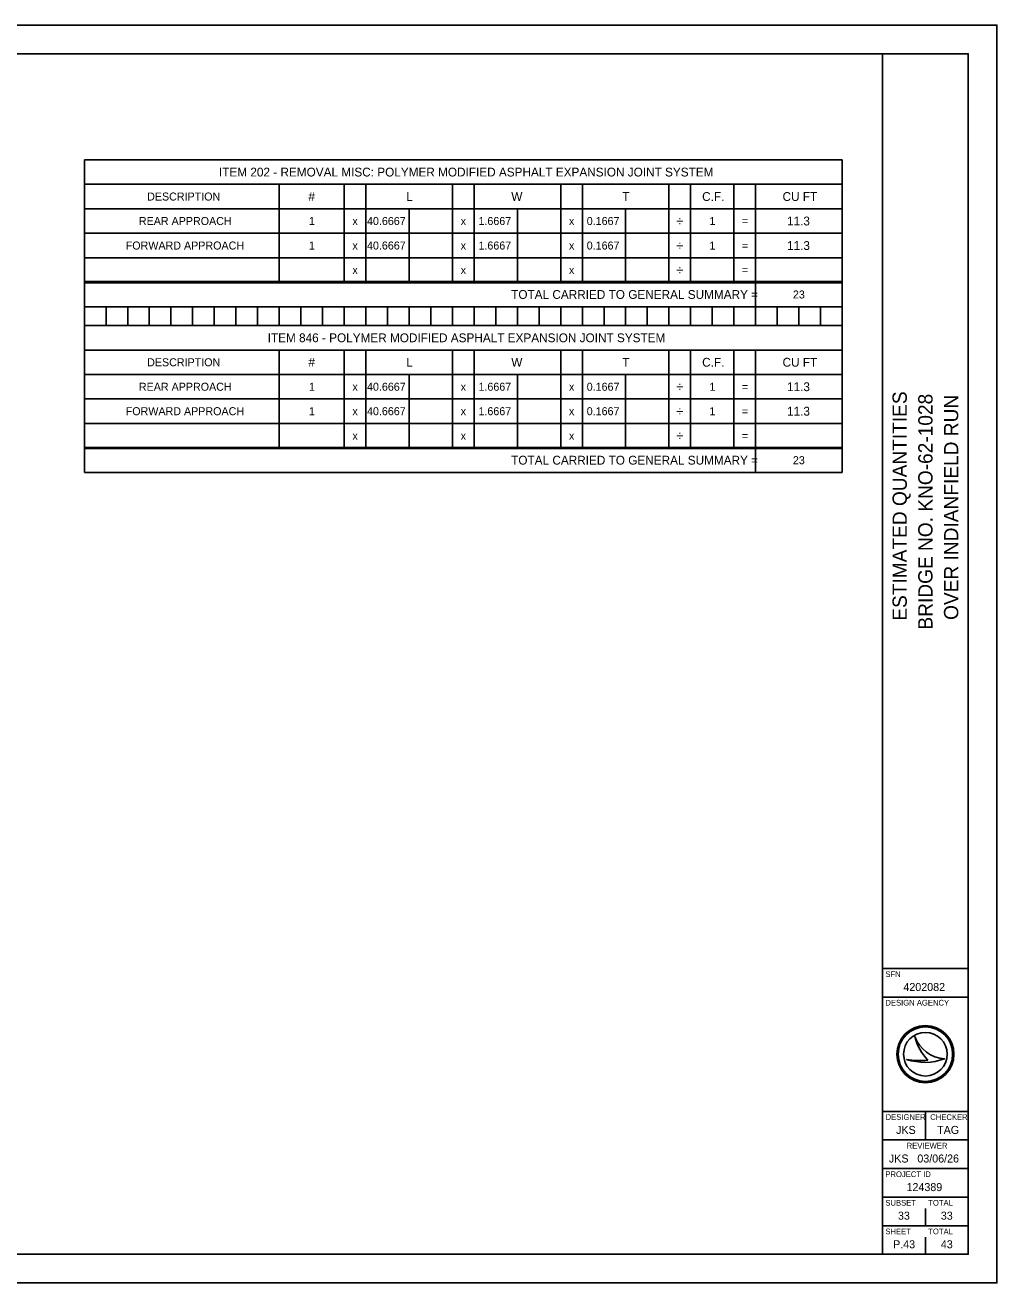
# Model space of a CAD drawing. Extents: x 0 to 34, y 0 to 22.
# Drawn here: x 17 to 34, y 0 to 22 of the extents above; entities that cross this region are included whole.
import ezdxf

# ---------------------------------------------------------------- set-up
doc = ezdxf.new("R2010")
doc.units = 0
for name, color, linetype in [('SH_Border', 7, 'Continuous'), ('SH_Cut_Line', 7, 'Continuous'), ('SH_Data', 7, 'Continuous'), ('SH_Text', 7, 'Continuous')]:
    doc.layers.add(name, color=color, linetype=linetype)

msp = doc.modelspace()

# ---------------------------------------------------------------- linework, layer by layer
at = {"layer": 'SH_Border'}
for p, q in [((32, 0.5), (32, 21.5)), ((32, 5.5), (33.5, 5.5)), ((32, 5), (33.5, 5)), ((32, 3), (33.5, 3)), ((32.75, 3), (32.75, 2.5)), ((32, 2.5), (33.5, 2.5)), ((32, 2), (33.5, 2)), ((32, 1.5), (33.5, 1.5)), ((32, 1), (33.5, 1))]:
    msp.add_line(p, q, dxfattribs=at)
msp.add_lwpolyline([(1.5, 21.5), (33.5, 21.5), (33.5, 0.5), (1.5, 0.5)], close=True, dxfattribs=at)
at = {"layer": 'SH_Cut_Line'}
msp.add_lwpolyline([(0, 0), (34, 0), (34, 22), (0, 22)], close=True, dxfattribs=at)
at = {"layer": 'SH_Data'}
for p, q in [((32.567, 4.31), (32.567, 4.31)), ((32.75, 4), (32.75, 4)), ((32.417, 3.91), (32.417, 3.91)), ((33.087, 3.919), (33.087, 3.919)), ((32.75, 1), (32.75, 1.3)), ((32.375, 0.675), (32.375, 0.675)), ((32.75, 0.5), (32.75, 0.8))]:
    msp.add_line(p, q, dxfattribs=at)
for radius in [0.5, 0.477, 0.477, 0.382]:
    msp.add_circle((32.75, 4), radius, dxfattribs=at)
for centre, radius, start, end in [((33.116, 4.498), 0.58, 198.9257, 198.9319), ((33.347, 4.47), 0.796, 191.6379, 191.6421), ((33.116, 4.498), 0.58, 198.9319, 267.1657), ((33.347, 4.47), 0.796, 191.6421, 226.0947), ((32.739, 4.87), 1.013, 251.4576, 290.0832), ((32.648, 5.154), 1.266, 259.4964, 259.4995), ((32.739, 4.87), 1.013, 251.4527, 251.4576), ((32.648, 5.154), 1.266, 259.4995, 276.6672)]:
    msp.add_arc(centre, radius, start, end, dxfattribs=at)
at = {"layer": 'SH_Text'}
for p, q in [((18.036, 19.644), (31.295, 19.644)), ((18.036, 19.644), (18.036, 17.492)), ((31.295, 19.644), (31.295, 17.492)), ((18.036, 19.216), (31.295, 19.216)), ((21.445, 19.216), (21.445, 17.514)), ((22.582, 19.216), (22.582, 17.514)), ((22.961, 19.216), (22.961, 17.514)), ((24.476, 19.216), (24.476, 17.514)), ((24.855, 19.216), (24.855, 17.514)), ((26.37, 19.216), (26.37, 17.514)), ((26.749, 19.216), (26.749, 17.514)), ((28.264, 19.216), (28.264, 17.514)), ((28.643, 19.216), (28.643, 17.514)), ((29.401, 19.216), (29.401, 17.514)), ((29.779, 19.216), (29.779, 17.514)), ((18.036, 18.788), (31.295, 18.788)), ((23.718, 18.788), (23.718, 17.514)), ((25.612, 18.788), (25.612, 17.514)), ((27.506, 18.788), (27.506, 17.514)), ((18.036, 18.36), (31.295, 18.36)), ((18.036, 17.931), (31.295, 17.931)), ((18.036, 17.514), (31.295, 17.514)), ((18.036, 17.514), (18.036, 14.593)), ((18.036, 17.492), (31.295, 17.492)), ((29.779, 17.492), (29.779, 17.075)), ((31.295, 17.514), (31.295, 14.593)), ((18.036, 17.075), (31.295, 17.075)), ((18.036, 16.745), (31.295, 16.745)), ((18.036, 16.317), (31.295, 16.317)), ((21.445, 16.317), (21.445, 14.615)), ((22.582, 16.317), (22.582, 14.615)), ((22.961, 16.317), (22.961, 14.615)), ((24.476, 16.317), (24.476, 14.615)), ((24.855, 16.317), (24.855, 14.615)), ((26.37, 16.317), (26.37, 14.615)), ((26.749, 16.317), (26.749, 14.615)), ((28.264, 16.317), (28.264, 14.615)), ((28.643, 16.317), (28.643, 14.615)), ((29.401, 16.317), (29.401, 14.615)), ((29.779, 16.317), (29.779, 14.615)), ((18.036, 15.889), (31.295, 15.889)), ((23.718, 15.889), (23.718, 14.615)), ((25.612, 15.889), (25.612, 14.615)), ((27.506, 15.889), (27.506, 14.615)), ((18.036, 15.461), (31.295, 15.461)), ((18.036, 15.032), (31.295, 15.032)), ((18.036, 14.615), (31.295, 14.615)), ((18.036, 14.615), (18.036, 14.176)), ((18.036, 14.593), (31.295, 14.593)), ((29.779, 14.593), (29.779, 14.176)), ((31.295, 14.615), (31.295, 14.176)), ((18.036, 14.176), (31.295, 14.176))]:
    msp.add_line(p, q, dxfattribs=at)
for points in [[(18.036, 17.075), (18.415, 17.075), (18.415, 16.745), (18.036, 16.745)], [(18.415, 17.075), (18.794, 17.075), (18.794, 16.745), (18.415, 16.745)], [(18.794, 17.075), (19.172, 17.075), (19.172, 16.745), (18.794, 16.745)], [(19.172, 17.075), (19.551, 17.075), (19.551, 16.745), (19.172, 16.745)], [(19.551, 17.075), (19.93, 17.075), (19.93, 16.745), (19.551, 16.745)], [(19.93, 17.075), (20.309, 17.075), (20.309, 16.745), (19.93, 16.745)], [(20.309, 17.075), (20.688, 17.075), (20.688, 16.745), (20.309, 16.745)], [(20.688, 17.075), (21.066, 17.075), (21.066, 16.745), (20.688, 16.745)], [(21.066, 17.075), (21.445, 17.075), (21.445, 16.745), (21.066, 16.745)], [(21.445, 17.075), (21.824, 17.075), (21.824, 16.745), (21.445, 16.745)], [(21.824, 17.075), (22.203, 17.075), (22.203, 16.745), (21.824, 16.745)], [(22.203, 17.075), (22.582, 17.075), (22.582, 16.745), (22.203, 16.745)], [(22.582, 17.075), (22.961, 17.075), (22.961, 16.745), (22.582, 16.745)], [(22.961, 17.075), (23.339, 17.075), (23.339, 16.745), (22.961, 16.745)], [(23.339, 17.075), (23.718, 17.075), (23.718, 16.745), (23.339, 16.745)], [(23.718, 17.075), (24.097, 17.075), (24.097, 16.745), (23.718, 16.745)], [(24.097, 17.075), (24.476, 17.075), (24.476, 16.745), (24.097, 16.745)], [(24.476, 17.075), (24.855, 17.075), (24.855, 16.745), (24.476, 16.745)], [(24.855, 17.075), (25.234, 17.075), (25.234, 16.745), (24.855, 16.745)], [(25.234, 17.075), (25.612, 17.075), (25.612, 16.745), (25.234, 16.745)], [(25.612, 17.075), (25.991, 17.075), (25.991, 16.745), (25.612, 16.745)], [(25.991, 17.075), (26.37, 17.075), (26.37, 16.745), (25.991, 16.745)], [(26.37, 17.075), (26.749, 17.075), (26.749, 16.745), (26.37, 16.745)], [(26.749, 17.075), (27.128, 17.075), (27.128, 16.745), (26.749, 16.745)], [(27.128, 17.075), (27.506, 17.075), (27.506, 16.745), (27.128, 16.745)], [(27.506, 17.075), (27.885, 17.075), (27.885, 16.745), (27.506, 16.745)], [(27.885, 17.075), (28.264, 17.075), (28.264, 16.745), (27.885, 16.745)], [(28.264, 17.075), (28.643, 17.075), (28.643, 16.745), (28.264, 16.745)], [(28.643, 17.075), (29.022, 17.075), (29.022, 16.745), (28.643, 16.745)], [(29.022, 17.075), (29.401, 17.075), (29.401, 16.745), (29.022, 16.745)], [(29.401, 17.075), (29.779, 17.075), (29.779, 16.745), (29.401, 16.745)], [(29.779, 17.075), (30.158, 17.075), (30.158, 16.745), (29.779, 16.745)], [(30.158, 17.075), (30.537, 17.075), (30.537, 16.745), (30.158, 16.745)], [(30.537, 17.075), (30.916, 17.075), (30.916, 16.745), (30.537, 16.745)], [(30.916, 17.075), (31.295, 17.075), (31.295, 16.745), (30.916, 16.745)]]:
    msp.add_lwpolyline(points, close=True, dxfattribs=at)

# ---------------------------------------------------------------- texts
at = {"layer": 'SH_Data'}
for s, p in [('ESTIMATED QUANTITIES', (32.425, 11.582)), ('BRIDGE NO. KNO-62-1028', (32.875, 11.427)), ('OVER INDIANFIELD RUN', (33.325, 11.596))]:
    msp.add_text(s, height=0.25, rotation=90, dxfattribs=at).set_placement(p)
for s, height, p in [('SFN', 0.1, (32.05, 5.35)), ('4202082', 0.14, (32.365, 5.105)), ('DESIGN AGENCY', 0.1, (32.05, 4.85)), ('DESIGNER', 0.1, (32.054, 2.85)), ('CHECKER', 0.1, (32.835, 2.85)), ('JKS', 0.14, (32.237, 2.605)), ('TAG', 0.14, (32.955, 2.605)), ('REVIEWER', 0.1, (32.422, 2.35)), ('JKS', 0.14, (32.112, 2.105)), ('03/06/26', 0.14, (32.609, 2.105)), ('PROJECT ID', 0.1, (32.05, 1.85)), ('124389', 0.14, (32.42, 1.605)), ('SUBSET', 0.1, (32.05, 1.35)), ('TOTAL', 0.1, (32.8, 1.35)), ('33', 0.14, (32.27, 1.105)), ('33', 0.14, (33.02, 1.105)), ('SHEET', 0.1, (32.05, 0.85)), ('TOTAL', 0.1, (32.8, 0.85)), ('P.43', 0.14, (32.185, 0.605)), ('43', 0.14, (33.02, 0.605))]:
    msp.add_text(s, height=height, dxfattribs=at).set_placement(p)
at = {"layer": 'SH_Text'}
for s, height, p in [('ITEM 202 - REMOVAL MISC: POLYMER MODIFIED ASPHALT EXPANSION JOINT SYSTEM', 0.154, (20.391, 19.353)), ('DESCRIPTION', 0.14, (19.134, 18.932)), ('#', 0.154, (21.955, 18.925)), ('L', 0.154, (23.668, 18.925)), ('W', 0.154, (25.505, 18.925)), ('T', 0.154, (27.447, 18.925)), ('C.F.', 0.154, (28.844, 18.925)), ('CU FT', 0.154, (30.251, 18.925)), ('REAR APPROACH', 0.14, (18.99, 18.504)), ('1', 0.14, (21.964, 18.504)), ('x', 0.14, (22.726, 18.504)), ('40.6667', 0.14, (22.981, 18.504)), ('x', 0.14, (24.62, 18.504)), ('1.6667', 0.14, (24.931, 18.504)), ('x', 0.14, (26.514, 18.504)), ('0.1667', 0.14, (26.825, 18.504)), ('÷', 0.168, (28.392, 18.49)), ('1', 0.14, (28.972, 18.504)), ('=', 0.14, (29.54, 18.504)), ('11.3', 0.154, (30.329, 18.497)), ('FORWARD APPROACH', 0.14, (18.76, 18.075)), ('1', 0.14, (21.964, 18.075)), ('x', 0.14, (22.726, 18.075)), ('40.6667', 0.14, (22.981, 18.075)), ('x', 0.14, (24.62, 18.075)), ('1.6667', 0.14, (24.931, 18.075)), ('x', 0.14, (26.514, 18.075)), ('0.1667', 0.14, (26.825, 18.075)), ('÷', 0.168, (28.392, 18.061)), ('1', 0.14, (28.972, 18.075)), ('=', 0.14, (29.54, 18.075)), ('11.3', 0.154, (30.329, 18.068)), ('x', 0.14, (22.726, 17.647)), ('x', 0.14, (24.62, 17.647)), ('x', 0.14, (26.514, 17.647)), ('÷', 0.168, (28.392, 17.633)), ('=', 0.14, (29.54, 17.647)), ('TOTAL CARRIED TO GENERAL SUMMARY =', 0.154, (25.503, 17.212)), ('23', 0.14, (30.432, 17.219)), ('ITEM 846 - POLYMER MODIFIED ASPHALT EXPANSION JOINT SYSTEM', 0.154, (21.243, 16.454)), ('DESCRIPTION', 0.14, (19.134, 16.033)), ('#', 0.154, (21.955, 16.026)), ('L', 0.154, (23.668, 16.026)), ('W', 0.154, (25.505, 16.026)), ('T', 0.154, (27.447, 16.026)), ('C.F.', 0.154, (28.844, 16.026)), ('CU FT', 0.154, (30.251, 16.026)), ('REAR APPROACH', 0.14, (18.99, 15.605)), ('1', 0.14, (21.964, 15.605)), ('x', 0.14, (22.726, 15.605)), ('40.6667', 0.14, (22.981, 15.605)), ('x', 0.14, (24.62, 15.605)), ('1.6667', 0.14, (24.931, 15.605)), ('x', 0.14, (26.514, 15.605)), ('0.1667', 0.14, (26.825, 15.605)), ('÷', 0.168, (28.392, 15.591)), ('1', 0.14, (28.972, 15.605)), ('=', 0.14, (29.54, 15.605)), ('11.3', 0.154, (30.329, 15.598)), ('FORWARD APPROACH', 0.14, (18.76, 15.177)), ('1', 0.14, (21.964, 15.177)), ('x', 0.14, (22.726, 15.177)), ('40.6667', 0.14, (22.981, 15.177)), ('x', 0.14, (24.62, 15.177)), ('1.6667', 0.14, (24.931, 15.177)), ('x', 0.14, (26.514, 15.177)), ('0.1667', 0.14, (26.825, 15.177)), ('÷', 0.168, (28.392, 15.163)), ('1', 0.14, (28.972, 15.177)), ('=', 0.14, (29.54, 15.177)), ('11.3', 0.154, (30.329, 15.17)), ('x', 0.14, (22.726, 14.748)), ('x', 0.14, (24.62, 14.748)), ('x', 0.14, (26.514, 14.748)), ('÷', 0.168, (28.392, 14.734)), ('=', 0.14, (29.54, 14.748)), ('TOTAL CARRIED TO GENERAL SUMMARY =', 0.154, (25.503, 14.313)), ('23', 0.14, (30.432, 14.32))]:
    msp.add_text(s, height=height, dxfattribs=at).set_placement(p)

doc.saveas('drawing.dxf')
